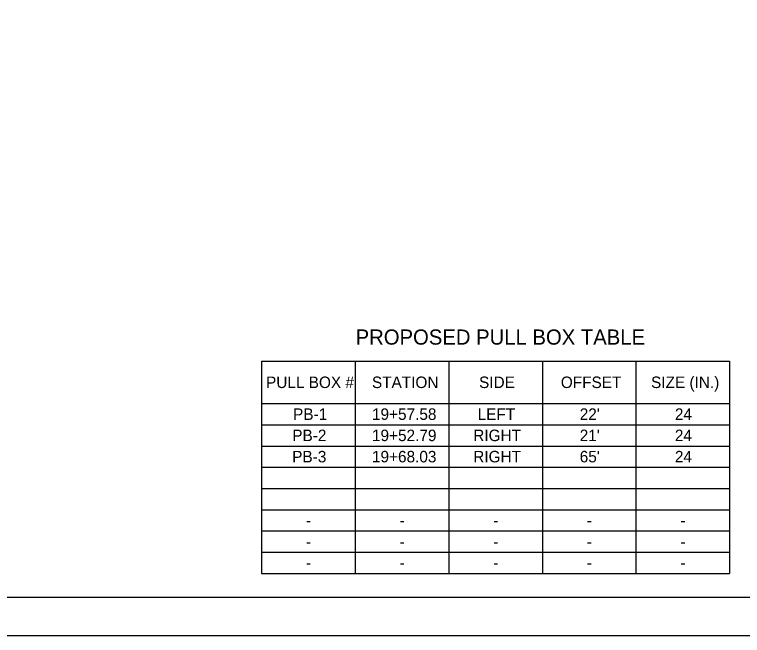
# Model space of a CAD drawing. Extents: x 0 to 34, y 0 to 22.
# Drawn here: x 17 to 26.61, y 0 to 8.19 of the extents above; entities that cross this region are included whole.
import ezdxf

# ---------------------------------------------------------------- set-up
doc = ezdxf.new("R2010")
doc.units = 0
for name, color, linetype in [('PM_P_Stop_Line', 7, 'Continuous'), ('SG_P_Heads', 7, 'Continuous'), ('UT_X_Electric', 7, 'Continuous')]:
    doc.layers.add(name, color=color, linetype=linetype)

msp = doc.modelspace()

# ---------------------------------------------------------------- linework, layer by layer
at = {"layer": 'PM_P_Stop_Line'}
msp.add_lwpolyline([(1.5, 21.5), (33.5, 21.5), (33.5, 0.5), (1.5, 0.5)], close=True, dxfattribs=at)
at = {"layer": 'SG_P_Heads'}
msp.add_lwpolyline([(0, 0), (34, 0), (34, 22), (0, 22)], close=True, dxfattribs=at)
at = {"layer": 'UT_X_Electric'}
for p, q in [((20.2598, 3.6177), (26.4363, 3.6177)), ((20.2598, 3.6177), (20.2598, 0.8177)), ((21.4951, 3.6177), (21.4951, 0.8177)), ((22.7304, 3.6177), (22.7304, 0.8177)), ((23.9657, 3.6177), (23.9657, 0.8177)), ((25.201, 3.6177), (25.201, 0.8177)), ((26.4363, 3.6177), (26.4363, 0.8177)), ((20.2598, 3.0577), (26.4363, 3.0577)), ((20.2598, 2.7777), (26.4363, 2.7777)), ((20.2598, 2.4977), (26.4363, 2.4977)), ((20.2598, 2.2177), (26.4363, 2.2177)), ((20.2598, 1.9377), (26.4363, 1.9377)), ((20.2598, 1.6577), (26.4363, 1.6577)), ((20.2598, 1.3777), (26.4363, 1.3777)), ((20.2598, 1.0977), (26.4363, 1.0977)), ((20.2598, 0.8177), (26.4363, 0.8177))]:
    msp.add_line(p, q, dxfattribs=at)

# ---------------------------------------------------------------- texts
for s, height, p in [('PROPOSED PULL BOX TABLE', 0.2, (21.5012, 3.8342)), ('PULL BOX #', 0.15153, (20.3191, 3.2619)), ('STATION', 0.15153, (21.7163, 3.2619)), ('SIDE', 0.15153, (23.1304, 3.2619)), ('OFFSET', 0.15153, (24.2094, 3.2619)), ('SIZE (IN.)', 0.15153, (25.4002, 3.2619)), ('PB-1', 0.15153, (20.6758, 2.8419)), ('19+57.58', 0.15153, (21.7172, 2.8419)), ('LEFT', 0.15153, (23.1118, 2.8419)), ("22'", 0.15153, (24.4589, 2.8419)), ('24', 0.15153, (25.7149, 2.8419)), ('PB-2', 0.15153, (20.6652, 2.5619)), ('19+52.79', 0.15153, (21.7173, 2.5619)), ('RIGHT', 0.15153, (23.0536, 2.5619)), ("21'", 0.15153, (24.4589, 2.5619)), ('24', 0.15153, (25.7149, 2.5619)), ('PB-3', 0.15153, (20.6645, 2.2819)), ('19+68.03', 0.15153, (21.717, 2.2819)), ('RIGHT', 0.15153, (23.0536, 2.2819)), ("65'", 0.15153, (24.4589, 2.2819)), ('24', 0.15153, (25.7149, 2.2819)), ('-', 0.1515, (20.8464, 1.4419)), ('-', 0.1515, (22.0817, 1.4419)), ('-', 0.1515, (23.317, 1.4419)), ('-', 0.1515, (24.5523, 1.4419)), ('-', 0.1515, (25.7876, 1.4419)), ('-', 0.1515, (20.8464, 1.1619)), ('-', 0.1515, (22.0817, 1.1619)), ('-', 0.1515, (23.317, 1.1619)), ('-', 0.1515, (24.5523, 1.1619)), ('-', 0.1515, (25.7876, 1.1619)), ('-', 0.1515, (20.8464, 0.8819)), ('-', 0.1515, (22.0817, 0.8819)), ('-', 0.1515, (23.317, 0.8819)), ('-', 0.1515, (24.5523, 0.8819)), ('-', 0.1515, (25.7876, 0.8819))]:
    msp.add_text(s, height=height, dxfattribs=at).set_placement(p)

doc.saveas('drawing.dxf')
